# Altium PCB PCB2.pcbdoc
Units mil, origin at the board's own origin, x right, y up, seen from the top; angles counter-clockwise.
Board outline 2311.1 x 2236.23 mil, 4 copper layers (Top Layer, Inner1, 内层2, Bottom Layer); 31 components, 18 nets, 99 pads, 262 vias.
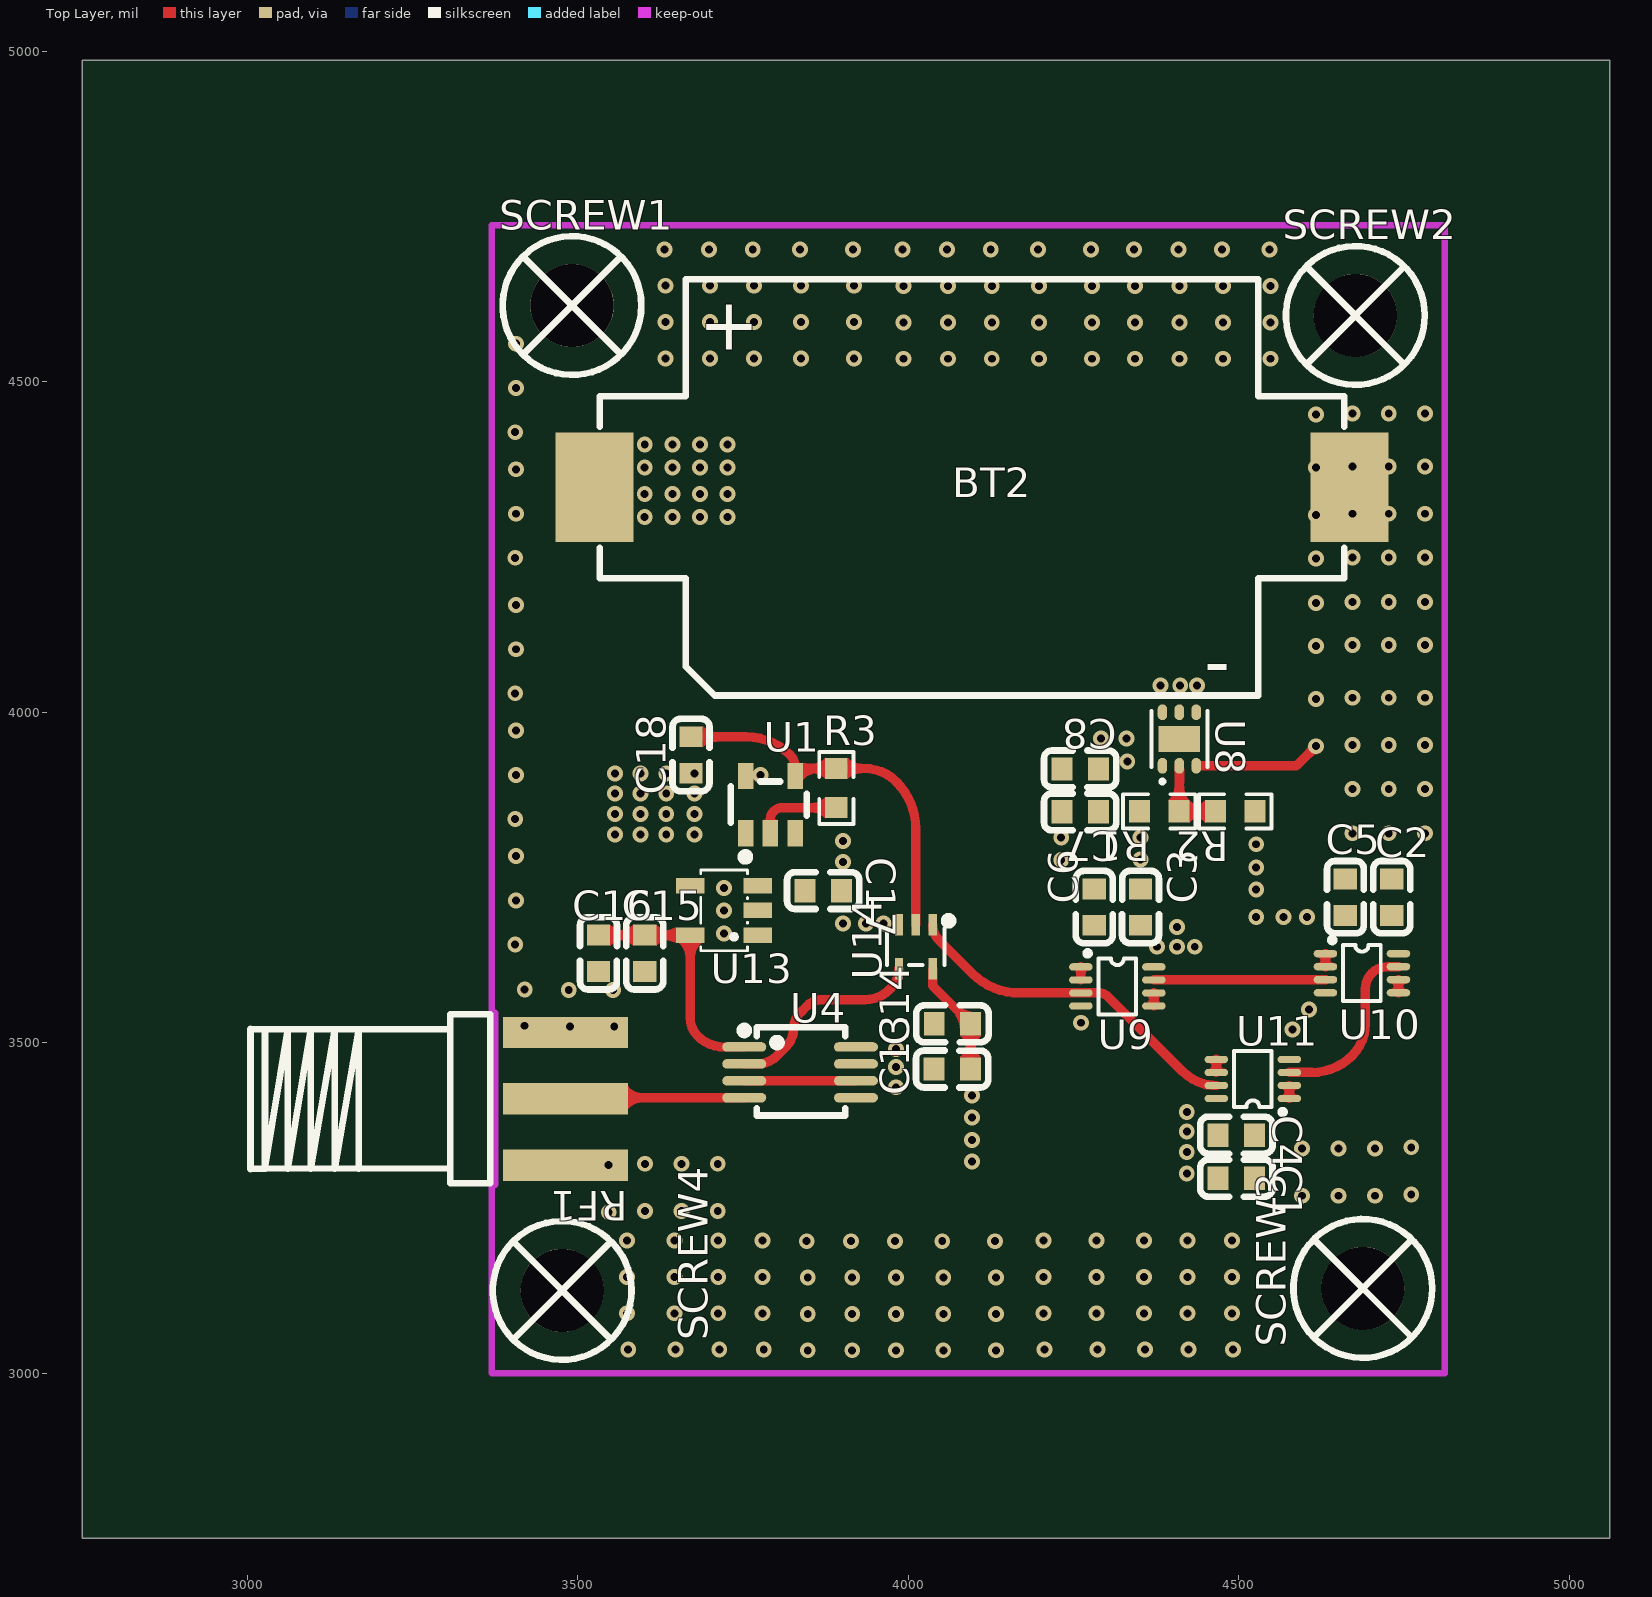
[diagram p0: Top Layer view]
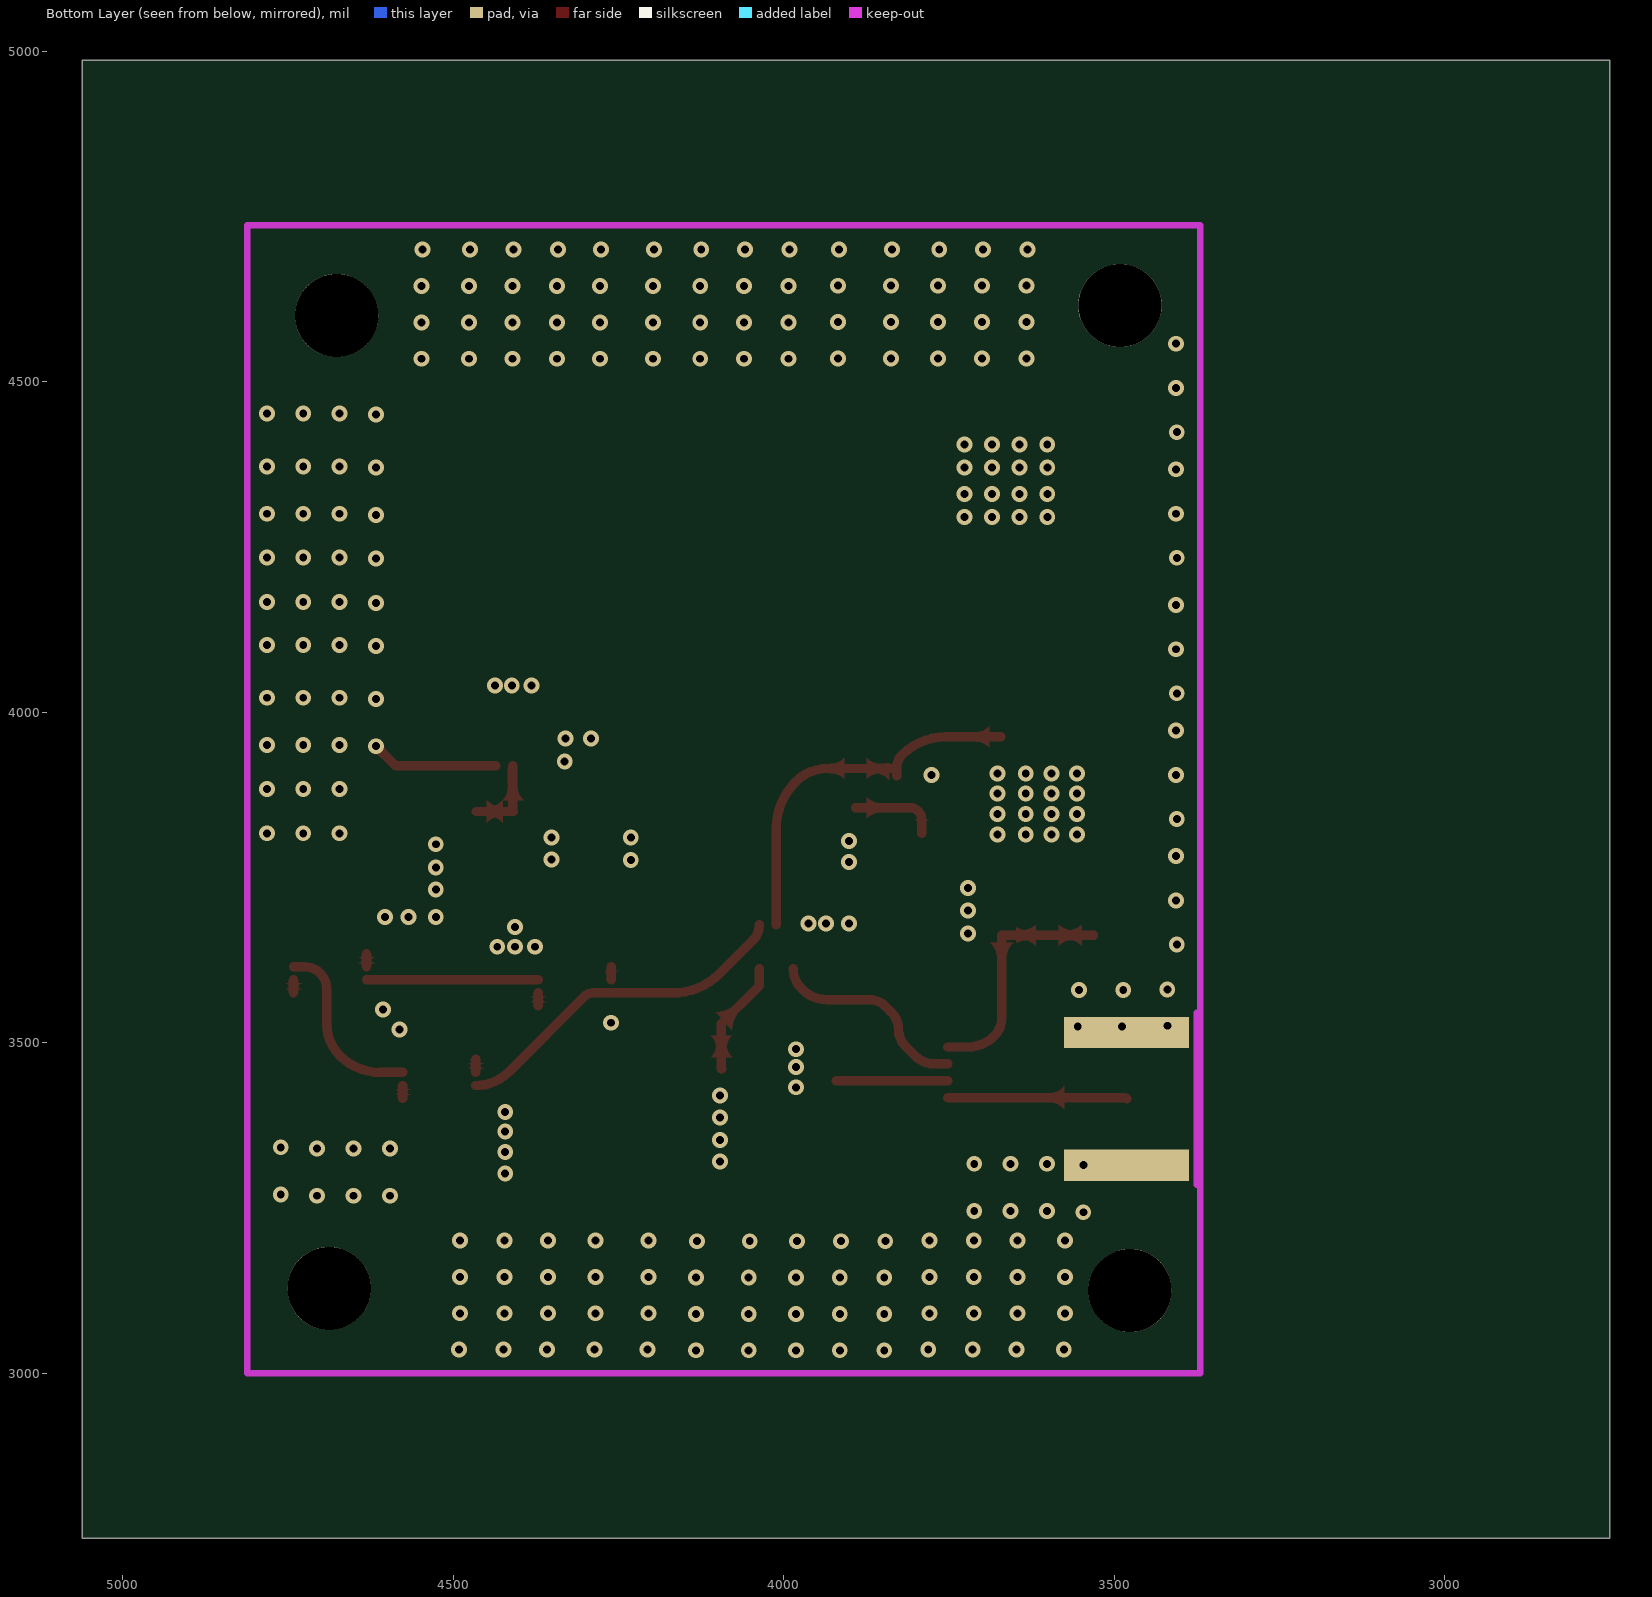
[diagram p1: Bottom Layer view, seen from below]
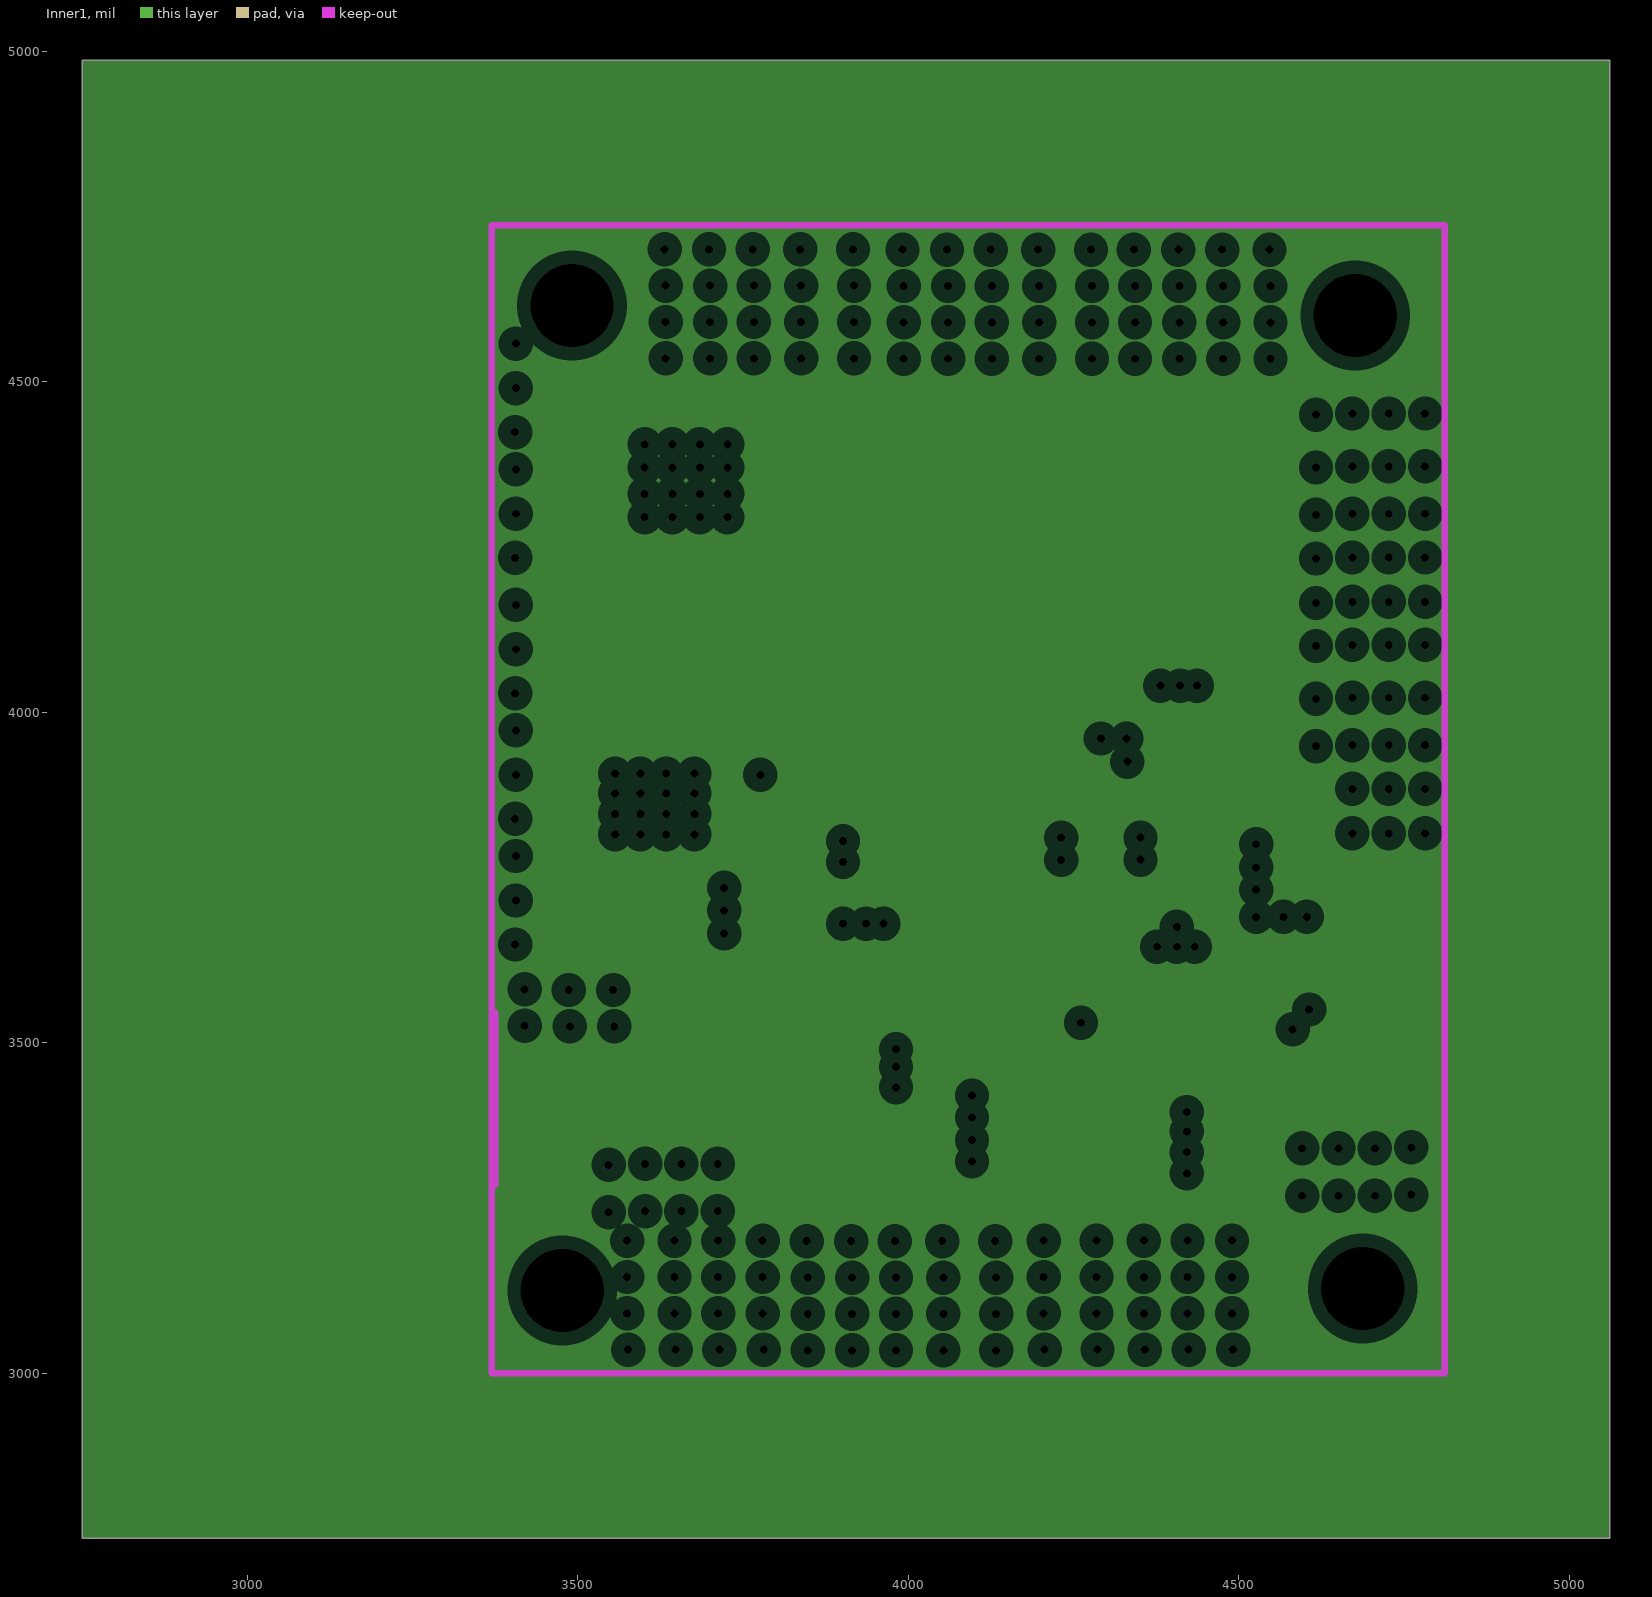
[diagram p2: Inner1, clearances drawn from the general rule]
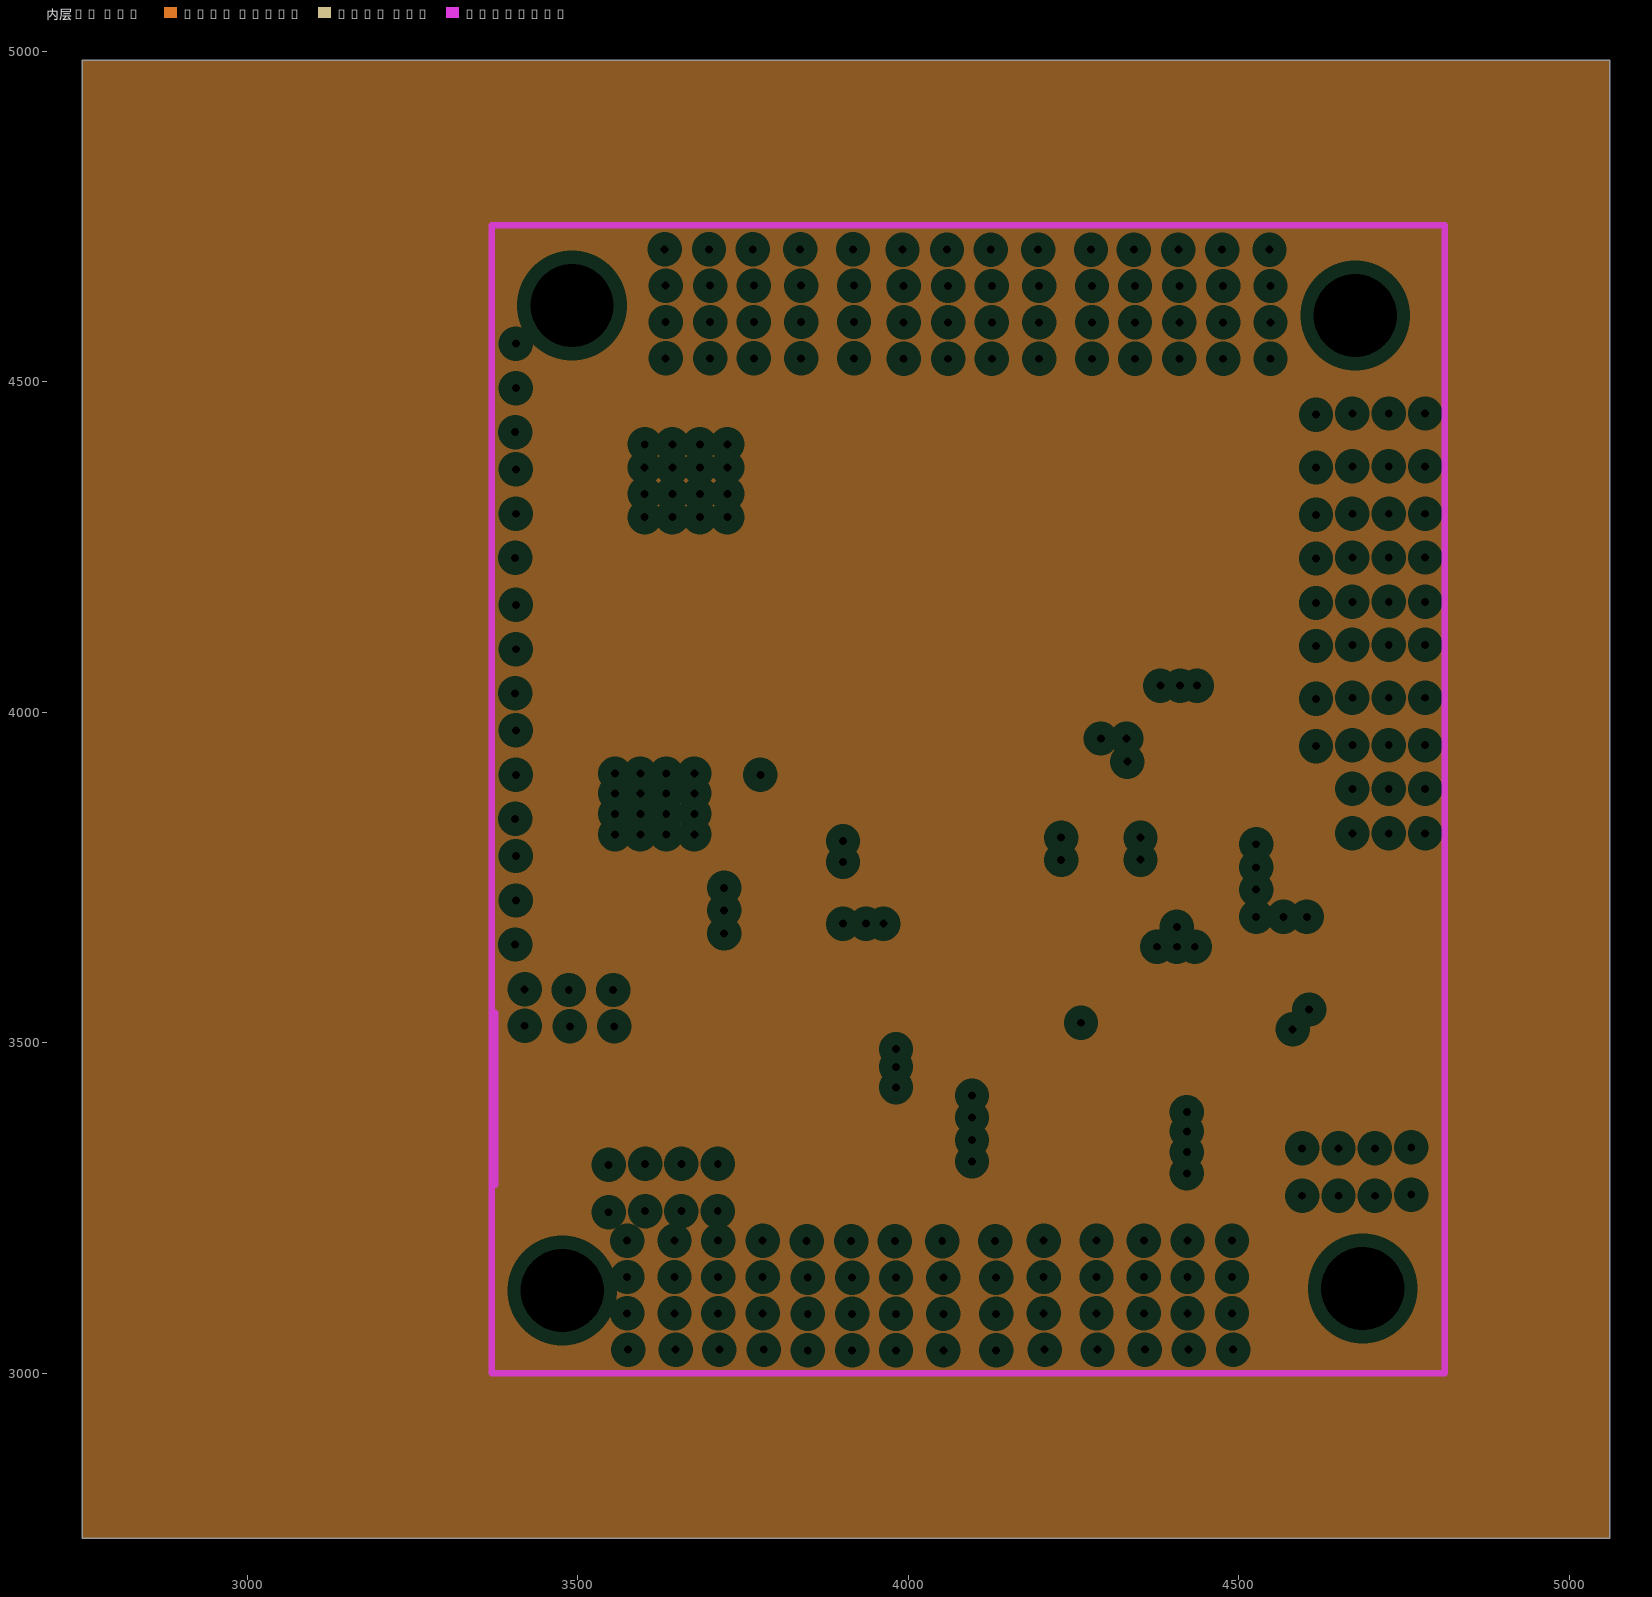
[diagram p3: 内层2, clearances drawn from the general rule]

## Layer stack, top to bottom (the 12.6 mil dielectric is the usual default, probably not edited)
Top Layer: signal copper (thickness not stored)
Dielectric: dielectric 12.6, FR-4, Dk 4.8
Inner1: plane copper (thickness not stored)
Dielectric: dielectric 12.6, FR-4, Dk 4.8
内层2: plane copper (thickness not stored)
Dielectric: dielectric 12.6, FR-4, Dk 4.8
Bottom Layer: signal copper (thickness not stored)

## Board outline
5061.1,2750 2750,2750 2750,4986.23 5061.1,4986.23

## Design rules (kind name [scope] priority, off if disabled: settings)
BoardOutlineClearance copperThickness1oz [All] p0: genericclearance=10 ignorepadtopadclearanceinfootprint=FALSE except(0: Arc-SplitContinuation Track-SplitContinuation SMDPad-SplitContinuation THPad-SplitContinuation Via-SplitContinuation Fill-SplitContinuation Poly-SplitContinuation Region-SplitContinuation Text-SplitContinuation; 6: Track-CutoutEdge SMDPad-CutoutEdge THPad-CutoutEdge Via-CutoutEdge Region-CutoutEdge; 11.8: Track-OutlineEdge SMDPad-OutlineEdge THPad-OutlineEdge Via-OutlineEdge Fill-OutlineEdge Region-OutlineEdge Poly-OutlineEdge Text-OutlineEdge Fill-CutoutEdge)
BoardOutlineClearance copperThickness2oz [All] p0: genericclearance=10 ignorepadtopadclearanceinfootprint=FALSE except(0: Arc-SplitContinuation Track-SplitContinuation SMDPad-SplitContinuation THPad-SplitContinuation Via-SplitContinuation Fill-SplitContinuation Poly-SplitContinuation Region-SplitContinuation Text-SplitContinuation; 6: Track-CutoutEdge SMDPad-CutoutEdge THPad-CutoutEdge Via-CutoutEdge Region-CutoutEdge; 11.8: Track-OutlineEdge SMDPad-OutlineEdge THPad-OutlineEdge Via-OutlineEdge Fill-OutlineEdge Region-OutlineEdge Poly-OutlineEdge Text-OutlineEdge Fill-CutoutEdge)
Clearance copperThickness1oz [(InNet('+3V') OR InNet('GND') OR InNet('VCC') OR InNet('$1N1815') OR InNet('$1N1960') OR InNet('$1N1780') OR InNet('$1N1939') OR InNet('$1N1788') OR InNet('$1N1786') OR InNet('$1N1774') OR InNet('$1N1810') OR InNet('$1N1811') OR InNet('$1N1773') OR InNet('$1N1772') OR InNet('$1N1777') OR InNet('$1N1771') OR InNet('$1N1776') OR InNet('$1N1775'))] p1: gap=7 ignorepadtopadclearanceinfootprint=FALSE except(4: Track-Track; 6: Track-SMDPad SMDPad-SMDPad Track-THPad SMDPad-THPad THPad-THPad Track-Via SMDPad-Via THPad-Via Via-Via SMDPad-Fill THPad-Fill Via-Fill Fill-Fill Track-Region SMDPad-Region THPad-Region Via-Region Region-Region Track-Poly SMDPad-Poly THPad-Poly Via-Poly Fill-Poly Region-Poly Poly-Poly Track-Text SMDPad-Text THPad-Text Via-Text Fill-Text Region-Text Poly-Text Text-Text; 6.9: Track-Hole SMDPad-Hole THPad-Hole Via-Hole Fill-Hole Region-Hole Poly-Hole Text-Hole Sheet-Hole; 11.8: Track-Fill Fill-Region Track-Sheet SMDPad-Sheet THPad-Sheet Via-Sheet Fill-Sheet Region-Sheet Poly-Sheet Text-Sheet)
Clearance copperThickness2oz [All] p1: gap=7 ignorepadtopadclearanceinfootprint=FALSE except(6: Track-SMDPad SMDPad-SMDPad Track-THPad SMDPad-THPad THPad-THPad Track-Via SMDPad-Via THPad-Via Via-Via SMDPad-Fill THPad-Fill Via-Fill Fill-Fill Track-Region SMDPad-Region THPad-Region Via-Region Region-Region Track-Poly SMDPad-Poly THPad-Poly Via-Poly Fill-Poly Region-Poly Poly-Poly Track-Text SMDPad-Text THPad-Text Via-Text Fill-Text Region-Text Poly-Text Text-Text; 6.9: Track-Hole SMDPad-Hole THPad-Hole Via-Hole Fill-Hole Region-Hole Poly-Hole Text-Hole Sheet-Hole; 8: Track-Track; 11.8: Track-Fill Fill-Region Track-Sheet SMDPad-Sheet THPad-Sheet Via-Sheet Fill-Sheet Region-Sheet Poly-Sheet Text-Sheet)
DiffPairsRouting differentialPair [All] p1: maxuncoupledlength=10 minlimit=5.9843 maxlimit=5.9843 mostfreqgap=5.9843 toplayer_minwidth=5 toplayer_prefwidth=10 toplayer_maxwidth=100 bottomlayer_minwidth=5 bottomlayer_prefwidth=10 bottomlayer_maxwidth=100
PasteMaskExpansion pasteMaskExpansion [All] p1: expansion=0
PlaneConnect innerPlane [All] p1: planeconnectstyle=Relief reliefexpansion=20 reliefentries=4 reliefconductorwidth=10 reliefairgap=10
PolygonConnect copperRegion [All] p1: connectstyle=Direct reliefentries=4 reliefconductorwidth=10 polygonreliefangle="90 Angle" airgapwidth=10
RoutingVias viaSize [All] p1: viastyle="Through Hole" holewidth=12.0078 minholewidth=11.811 maxholewidth=248.0314 width=24.0158 minwidth=19.685 maxwidth=393.7008
SolderMaskExpansion solderMaskExpansion [All] p1: useseparateexpansions=TRUE expansion=2.0079 expansionbottom=2.0079
Width copperThickness1oz [All] p1: maxlimit=100 minlimit=5 preferedwidth=10
Width copperThickness2oz [All] p1: maxlimit=100 minlimit=8 preferedwidth=10

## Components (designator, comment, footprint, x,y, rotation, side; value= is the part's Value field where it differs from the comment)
BT2 "XDCR-2032-603" BAT-SMD_XDCR-2032-603 4096.1,4340 r0 top
C1 "CAP_0603" C0603 4496.1,3295 r0 top
C2 "CAP_0603" C0603 4731.1,3720 r90 top
C3 "CAP_0603" C0603 4351.1,3705 r90 top
C4 "CGA0603X5R105K500JT" C0603 4496.1,3360 r0 top
C5 "CGA0603X5R105K500JT" C0603 4661.1,3720 r90 top
C6 "CGA0603X5R105K500JT" C0603 4281.1,3705 r90 top
C7 "CAP_0603" C0603 4259.79,3848.93 r180 top
C8 "CGA0603X5R105K500JT" C0603 4259.79,3913.93 r180 top
C13 "CAP_0603" C0603 4066.1,3460 r0 top
C14 "CGA0603X5R105K500JT" C0603 4066.55,3528.37 r0 top
C15 "CAP_0603" C0603 3601.1,3635 r90 top
C16 "CGA0603X5R105K500JT" C0603 3531.1,3635 r90 top
C17 "CAP_0603" C0603 3871.1,3730 r180 top
C18 "CAP_0603" C0603 3671.1,3935 r90 top
R1 "Res_0603" R0603 4379.36,3849.65 r0 top
R2 "Res_0603" R0603 4494.36,3849.65 r0 top
R3 "Res_0603" R0603 3891.1,3885 r90 top
RF1 "BWSMA-KE-P001" SMA-SMD_BWSMA-KE-P001 3481.1,3415 r180 top
SCREW1 "M3螺丝" M3螺丝 3491.1,4615 r0 top
SCREW2 "M3螺丝" M3螺丝 4676.1,4600 r0 top
SCREW3 "M3螺丝" M3螺丝 4687.42,3128.15 r0 top
SCREW4 "M3螺丝" M3螺丝 3476.1,3125 r0 top
U1 "SN74AUP1G14DBVR" SOT-23-5_L2.9-W1.6-P0.95-LS2.8-BR 3791.1,3860 r270 top
U4 "ADG902BRMZ" MSOP-8_L3.0-W3.0-P0.65-LS5.0-BL 3836.1,3455 r270 top
U8 "TLV75801PDRVR" WSON-6_L2.0-W2.0-P0.65-TL-EP 4409.79,3959.2 r90 top
U9 "SN74AUP3G04DCUR" VSSOP-8_L2.3-W2.0-P0.50-LS3.1-BL 4316.1,3585 r270 top
U10 "SN74AUP3G04DCUR" VSSOP-8_L2.3-W2.0-P0.50-LS3.1-BL 4686.1,3605 r270 top
U11 "SN74AUP3G04DCUR" VSSOP-8_L2.3-W2.0-P0.50-LS3.1-BL 4521.1,3445 r90 top
U13 "TPS7A0518PDBVR" SOT-23-5_L3.0-W1.7-P0.95-LS2.8-BR 3721.1,3700 r0 top
U14 "74AUP1G86GW-TP" SOT-353_L2.1-W1.3-P0.65-LS2.3-BR 4011.1,3645 r90 top

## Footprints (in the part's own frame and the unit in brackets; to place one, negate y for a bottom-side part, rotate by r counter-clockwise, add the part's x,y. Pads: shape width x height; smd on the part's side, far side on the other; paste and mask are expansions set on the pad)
BAT-SMD_XDCR-2032-603 [mm]
  rect 3x4.2 smd: 1(-14.5,0) 2(14.5,0)
  silkscreen extent -14.3,-8 14.3,8
C0603 [mm]
  rect 0.8x0.9 smd: 1(-0.7,0) 2(0.7,0)
  silkscreen extent -1.39,-0.71 1.39,0.71
M3螺丝 [mil]
  round 126 hole 126: 1(0,0)
  silkscreen extent -105,-105 105,105
MSOP-8_L3.0-W3.0-P0.65-LS5.0-BL [mil]
  oval 14.33x66.61 smd: 1(-38.39,-84.49) 2(-12.79,-84.49) 3(12.8,-84.49) 4(38.39,-84.49) 5(38.39,84.49) 6(12.8,84.49) 7(-12.79,84.49) 8(-38.39,84.49)
  silkscreen extent -69,-90 65,68
R0603 [mil]
  rect 31.75x34.02 smd: 1(-29.66,0) 2(29.66,0)
  silkscreen extent -55,-26 55,26
SMA-SMD_BWSMA-KE-P001 [mm]
  rect 4.8x1.2 smd: 1(0,-2.55) 2(0,2.55) 5(0,0)
  rect 4.8x1.2 smd far side: 3(0,2.55) 4(0,-2.55)
  Board Outline Layer lines w0.254: 2.7,3.3 2.7,-3.3 2.7,3.3
  silkscreen extent 2.89,-3.25 12.1,3.25
SOT-23-5_L2.9-W1.6-P0.95-LS2.8-BR [mm]
  rect 1x0.6 smd: 1(1.1,-0.95) 2(1.1,0) 3(1.1,0.95) 4(-1.1,0.95) 5(-1.1,-0.95)
  silkscreen extent -0.89,-1.52 2.16,1.4
SOT-23-5_L3.0-W1.7-P0.95-LS2.8-BR [mm]
  rect 1.1x0.6 smd: 1(1.3,-0.95) 2(1.3,0) 3(1.3,0.95) 4(-1.3,0.95) 5(-1.3,-0.95)
  silkscreen extent -0.9,-1.55 0.9,1.55
SOT-353_L2.1-W1.3-P0.65-LS2.3-BR [mm]
  rect 0.839x0.315 smd: 1(0.844,-0.65) 2(0.844,0) 3(0.844,0.65) 4(-0.844,0.65) 5(-0.844,-0.65)
  silkscreen extent -0.7,-1.41 1.15,1.1
VSSOP-8_L2.3-W2.0-P0.50-LS3.1-BL [mm]
  oval 0.28x0.905 smd: 1(-0.75,-1.403) 2(-0.25,-1.403) 3(0.25,-1.403) 4(0.75,-1.403) 5(0.75,1.403) 6(0.25,1.403) 7(-0.25,1.403) 8(-0.75,1.403)
  silkscreen extent -1.37,-1.24 1.08,0.72
WSON-6_L2.0-W2.0-P0.65-TL-EP [mm]
  oval 0.607x0.364 smd: 1(-1.028,0.65) 2(-1.028,0) 3(-1.028,-0.65) 4(1.028,-0.65) 5(1.028,0) 6(1.028,0.65)
  rect 1x1.6 smd: 7(0,0)
  silkscreen extent -1.71,-1.08 1.08,1.08

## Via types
v1: diameter 24.02, hole 12.01, Top Layer to Bottom Layer, 262 vias

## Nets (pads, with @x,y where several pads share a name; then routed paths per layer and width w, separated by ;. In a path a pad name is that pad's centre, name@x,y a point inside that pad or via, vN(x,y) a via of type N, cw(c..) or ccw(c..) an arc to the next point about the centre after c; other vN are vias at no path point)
$1N1771: U10.1 U10.2 | length 19.7
  Top Layer w14.2: U10.2 U10.1
$1N1772: U10.5 U10.6 | length 19.7
  Top Layer w14.2: U10.5 U10.6
$1N1773: U9.1 U9.2 | length 19.7
  Top Layer w14.2: U9.2 U9.1
$1N1774: U9.5 U9.6 | length 19.7
  Top Layer w14.2: U9.5 U9.6
$1N1775: U11.1 U11.2 | length 19.7
  Top Layer w14.2: U11.1 U11.2
$1N1776: U11.5 U11.6 | length 19.7
  Top Layer w14.2: U11.6 U11.5
$1N1777: U10.7 U11.3 | length 277.4
  Top Layer w14.2: U11.3 4610.36,3454.84 ccw(c4610.36,3540.74) 4671.1,3480 ccw(c4622.82,3528.28) 4691.1,3528.28 4691.1,3580.86 cw(c4725.25,3580.86) 4701.1,3605 cw(c4724.86,3581.24) 4724.86,3614.84 U10.7
$1N1780: R1.2 R2.1 U8.2 | length 125
  Top Layer w14.2: U8.2 4409.79,3851.5 cw(c4407.17,3851.5) R1.2 R2.1
$1N1786: U4.2 U14.4 | length 310.9
  Top Layer w14.2: U4.2 3771.63,3467.79 ccw(c3771.63,3509.48) 3773.73,3467.84 cw(c3777.75,3449.37) 3777.81,3468.28 3777.97,3468.28 ccw(c3771.63,3509.48) 3801.1,3480 3815.5,3494.39 ccw(c3789.89,3520) 3826.1,3520 cw(c3862.32,3520) 3836.71,3545.61 3846.1,3555 cw(c3870.25,3530.86) 3870.25,3565 3934.89,3565 ccw(c3934.89,3616.21) 3971.1,3580 3973.24,3582.14 ccw(c3943.63,3611.76) U14.4
$1N1788: RF1.5 U4.4 | length 270.9
  Top Layer w14.2: RF1.5 cw(c3485,3411.1) 3485,3416.61 U4.4
$1N1810: U9.7 U10.3 | length 259.6
  Top Layer w14.2: U9.7 4630.11,3594.84 ccw(c4630.11,3595.93) U10.3
$1N1811: U9.3 U11.7 U14.1 | length 528.4
  Top Layer w14.2: U14.1 ccw(c4070.08,3678.24) 4046.47,3654.63 4096.65,3604.45 ccw(c4167.36,3675.16) 4167.36,3575.16 U9.3 4288.65,3575.16 cw(c4288.65,3557.54) 4301.1,3570 4414.77,3456.33 ccw(c4465.88,3507.44) 4445.49,3438.1 ccw(c4453.58,3454.84) 4453.41,3436.24 ccw(c4465.88,3507.44) U11.7
$1N1815: C15.2 C16.2 U4.1 U13.5 | length 369.4
  Top Layer w14.2: C16.2 C15.2 3669.82,3662.56 ccw(c3669.82,3662.7) U13.5 3669.92,3537 ccw(c3708.11,3537) 3681.1,3510 ccw(c3721.2,3550.1) 3721.2,3493.39 U4.1
$1N1939: R3.1 U1.2 | length 131.1
  Top Layer w14.2: U1.2 3791.1,3837.92 cw(c3808.19,3837.92) 3796.1,3850 cw(c3808.99,3837.11) 3808.99,3855.34 R3.1
$1N1960: C18.2 R3.2 U1.4 U14.2 | length 574.4
  Top Layer w14.2: C18.2 3754.57,3962.56 cw(c3754.57,3868.46) 3821.1,3935 cw(c3803.23,3917.12) U1.4@3828.51,3917.12 ; U1.4 U1.4@3828.51,3917.12 ; U14.2 4011.1,3823.58 ccw(c3911.1,3823.58) 3981.81,3894.29 3981.1,3895 ccw(c3933.64,3847.54) 3933.64,3914.66 R3.2 3834.45,3914.66 cw(c3834.45,3923.07) U1.4@3828.51,3917.12
+3V: BT2.1 C17.2 U8.4 U8.6 U13.1 U13.3
  other v1: 3721.1,3665 3721.1,3700 3721.1,3734.09 4381.1,4040 4411.1,4040 4436.63,4040 3601.06,4295 3642.9,4295 3684.5,4295 3726.1,4295 3601.06,4330 3642.9,4330 3684.5,4330 3726.1,4330 3601.06,4370 3642.9,4370 3684.5,4370 3726.1,4370 3601.1,4405 3642.94,4405 3684.55,4405 3726.15,4405
GND: BT2.2 C1.2 C2.2 C3.2 C4.2 C5.2 C6.2 C7.2 C8.2 C13.1 C14.1 C15.1 C16.1 C17.1 C18.1 R1.1 RF1.1 RF1.2 RF1.3 RF1.4 SCREW1.1 SCREW2.1 SCREW3.1 SCREW4.1 U1.3 U4.3 U4.5 U4.6 U4.7 U4.8 U8.3 U9.4 U10.4 U11.4 U13.2 U14.3 | length 362.5
  Top Layer w14.2: U4.3 U4.6 ; U8.3 4586.91,3918.72 v1(4616.58,3948.38)
  other v1: 3576.06,3035.48 3647.72,3035.48 3713.86,3035.48 3781.1,3035.48 3847.72,3034.52 3914.96,3034.52 3981.1,3034.52 4052.76,3034.52 4132.72,3034.52 4206.1,3035.48 4286.06,3035.48 4357.72,3035.48 4423.86,3035.48 4491.1,3035.48 3574.45,3090.48 3646.1,3090.48 3712.25,3090.48 3779.49,3090.48 3847.72,3089.52 3914.96,3089.52 3981.1,3089.52 4052.76,3089.52 4132.72,3089.52 4204.49,3090.48 4284.45,3090.48 4356.1,3090.48 4422.25,3090.48 4489.49,3090.48 3574.45,3145.48 3646.1,3145.48 3712.25,3145.48 3779.49,3145.48 3847.72,3144.52 3914.96,3144.52 3981.1,3144.52 4052.76,3144.52 4132.72,3144.52 4204.49,3145.48 4284.45,3145.48 4356.1,3145.48 4422.25,3145.48 4489.49,3145.48 3574.45,3200.48 3646.1,3200.48 3712.25,3200.48 3779.49,3200.48 3846.1,3199.52 3913.34,3199.52 3979.49,3199.52 4051.14,3199.52 4131.1,3199.52 4204.49,3200.48 4284.45,3200.48 4356.1,3200.48 4422.25,3200.48 4489.49,3200.48 3546.58,3243.38 3601.58,3245 3656.58,3245 3711.58,3245 4595.62,3268.34 4650.62,3268.34 4705.62,3268.34 4760.62,3269.96 3546.58,3315.04 3601.58,3316.66 3656.58,3316.66 3711.58,3316.66 4595.62,3340 4650.62,3340 4705.62,3340 4760.62,3341.62 3981.1,3432.39 3981.1,3463.25 3981.1,3490 4581.1,3520 3419.49,3525.48 3487.72,3524.52 3554.96,3524.52 4261.1,3530 4606.1,3550 3419.49,3580.48 3486.1,3579.52 3553.34,3579.52 3405.14,3648.38 3901.1,3680 3935.8,3680 3962.26,3680 3406.1,3715 3901.1,3773.27 4231.1,3776.21 4351.1,3776.7 3406.1,3782.24 3901.1,3805 4231.1,3810 4351.1,3810 3556.1,3815 3594.48,3815 3633.6,3815 3676.1,3815 4671.58,3816.62 4726.58,3816.62 4781.58,3816.62 3405.14,3838.38 3556.1,3845.95 3594.48,3845.95 3633.6,3845.95 3676.1,3845.95 3556.1,3876.98 3594.48,3876.98 3633.6,3876.98 3676.1,3876.98 4671.58,3883.86 4726.58,3883.86 4781.58,3883.86 3406.1,3905 3556.1,3906.99 3594.48,3906.99 3633.6,3906.99 3676.1,3906.99 4671.58,3950 4726.58,3950 4781.58,3950 3406.1,3972.24 4616.58,4020.04 4671.58,4021.66 4726.58,4021.66 4781.58,4021.66 3405.14,4028.38 3406.1,4095 4616.58,4100 4671.58,4101.62 4726.58,4101.62 4781.58,4101.62 3406.1,4162.24 4616.58,4165 4671.58,4166.62 4726.58,4166.62 4781.58,4166.62 4616.58,4232.24 3405.14,4233.38 4671.58,4233.86 4726.58,4233.86 4781.58,4233.86 4616.58,4298.38 3406.1,4300 4671.58,4300 4726.58,4300 4781.58,4300 3406.1,4367.24 4616.58,4370.04 4671.58,4371.66 4726.58,4371.66 4781.58,4371.66 3405.14,4423.38 4616.58,4450 4671.58,4451.62 4726.58,4451.62 4781.58,4451.62 3406.1,4490 3632.72,4535 3699.96,4535 3766.1,4535 3837.76,4535 3917.72,4535 3992.72,4534.52 4059.96,4534.52 4126.1,4534.52 4197.76,4534.52 4277.72,4534.52 4342.72,4534.52 4409.96,4534.52 4476.1,4534.52 4547.76,4534.52 3406.1,4557.24 3632.72,4590 3699.96,4590 3766.1,4590 3837.76,4590 3917.72,4590 3992.72,4589.52 4059.96,4589.52 4126.1,4589.52 4197.76,4589.52 4277.72,4589.52 4342.72,4589.52 4409.96,4589.52 4476.1,4589.52 4547.76,4589.52 3632.72,4645 3699.96,4645 3766.1,4645 3837.76,4645 3917.72,4645 3992.72,4644.52 4059.96,4644.52 4126.1,4644.52 4197.76,4644.52 4277.72,4644.52 4342.72,4644.52 4409.96,4644.52 4476.1,4644.52 4547.76,4644.52 3631.1,4700 3698.34,4700 3764.49,4700 3836.14,4700 3916.1,4700 3991.1,4699.52 4058.34,4699.52 4124.49,4699.52 4196.14,4699.52 4276.1,4699.52 4341.1,4699.52 4408.34,4699.52 4474.49,4699.52 4546.14,4699.52
VCC: C1.1 C2.1 C3.1 C4.1 C5.1 C6.1 C7.1 C8.1 C13.2 C14.2 R2.2 U1.5 U8.1 U9.8 U10.8 U11.8 U14.5 | length 175.7
  Top Layer w14.2: U14.5 4036.69,3585.78 C14.2 4094.11,3460.45 C13.2
  other v1: 4421.1,3302.24 4096.1,3320.06 4421.1,3334.25 4096.1,3352.4 4421.1,3365.61 4096.1,3386.7 4421.1,3395 4096.1,3420 4376.1,3645 4406.1,3645 4433.15,3645 4406.1,3675 4526.1,3690.17 4567.42,3690.17 4602.69,3690.17 4526.1,3731.33 4526.1,3765.13 4526.1,3800 3776.1,3905 4331.1,3925 4291.1,3960 4329.84,3960
pads on no net: U1.1 U8.5 U8.7 U13.4

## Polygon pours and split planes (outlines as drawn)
$1N1960 on Top Layer (solid, remove dead copper, pour order 0): 3533.93,3943.21 3533.93,4072.82 3687.89,4072.82 3687.89,3943.21
GND on Top Layer (solid, remove dead copper, pour order 2): 3536.1,3795 3536.1,3925 3691.1,3925 3691.1,3795
+3V on Bottom Layer (solid, remove dead copper, pour order 52): 3581.1,4425 3581.1,4260 3751.1,4260 3751.1,4422.77 3748.87,4425
+3V on Bottom Layer (solid, remove dead copper, pour order 54): 3706.1,3655 3751.1,3655 3751.1,4420 3706.1,4420
+3V on Bottom Layer (solid, remove dead copper, pour order 56): 3726.1,4060 4451.1,4060 4451.1,4025.03 3727.07,4025.03 3726.1,4026
GND on Top Layer (solid, remove dead copper, pour order 4): 3886.1,3505 3886.1,3405 4056.1,3405 4056.1,3505.19 3885.91,3505.19
+3V on Top Layer (solid, remove dead copper, pour order 6): 3466.1,4425 3756.1,4425 3756.1,4255 3466.1,4255
+3V on Top Layer (solid, remove dead copper, pour order 8): 3776.1,3750 3865.48,3750 3865.48,3711.03 3823.4,3711.03 3823.4,3723.64 3777.47,3723.64 3776.1,3725
GND on Top Layer (solid, remove dead copper, pour order 10): 4024.03,3544.13 4024.03,3491.29 4027.36,3487.96 4055.07,3487.96 4055.52,3488.4 4055.52,3528.37 4039.76,3544.13
+3V on Top Layer (solid, remove dead copper, pour order 12): 3771.1,3750 3711.1,3750 3711.1,3649.6 3770.7,3649.6 3771.1,3650 3771.1,3675.51 3738.22,3675.51 3738.22,3725.16 3771.76,3725.16 3771.76,3749.35
+3V on Top Layer (solid, remove dead copper, pour order 14): 4366.1,3985.36 4366.1,4055 4448.33,4055 4448.33,3986.23 4427.43,3986.23 4427.43,4019.33 4390.19,4019.33 4390.19,3985.36
VCC on Top Layer (solid, remove dead copper, pour order 16): 3756.1,3925 3793.6,3925 3793.6,3880 3755,3880 3755,3923.89
VCC on Top Layer (solid, remove dead copper, pour order 18): 4270.19,3929.67 4270.82,3929.04 4270.82,3830.52 4306.1,3830.52 4306.1,3900 4305.89,3905 4391.1,3905 4391.1,3931.3 4271.82,3931.3
VCC on Top Layer (solid, remove dead copper, pour order 20): 4271.51,3913.93 4271.51,3979.41 4349.9,3979.41 4349.9,3912.8 4272.64,3912.8
VCC on Top Layer (solid, remove dead copper, pour order 22): 4261.1,3695 4448.3,3695 4448.3,3610 4354.1,3610 4354.1,3650.28 4265.82,3650.28 4261.1,3655
VCC on Top Layer (solid, remove dead copper, pour order 24): 4636.72,3668.85 4717.25,3668.85 4721.1,3665 4721.1,3628.65 4759.75,3628.65 4761.1,3630 4761.1,3708.97 4633.15,3708.97 4633.15,3672.42
VCC on Top Layer (solid, remove dead copper, pour order 26): 4645.34,3665.28 4506.1,3665.28 4506.1,3873.41 4508.35,3875.66 4548.9,3875.66 4566.1,3858.45 4566.1,3710 4641.1,3710 4646.1,3705 4646.1,3666.04
VCC on Top Layer (solid, remove dead copper, pour order 28): 4401.1,3420.81 4401.1,3270.63 4486.1,3270.63 4486.1,3420.81
GND on Top Layer (solid, remove dead copper, pour order 30): 4633.16,3731.03 4805.62,3731.03 4805.62,4715.48 4796.1,4725 3381.1,4725 3376.1,4720 3376.1,4510 3381.1,4505 4581.1,4505 4591.1,4495 4591.1,3920 4636.1,3875 4636.1,3733.97
GND on Top Layer (solid, remove dead copper, pour order 32): 3374.8,3338.62 3374.8,3005 4806.1,3005 4811.1,3000 4811.1,3747.66 4778.44,3747.66 4776.1,3750 4776.1,3385 4775.46,3384.36 4506.2,3384.36 4506.2,3225 3761.1,3225 3761.1,3337.01 3759.5,3338.62
GND on Top Layer (solid, remove dead copper, pour order 34): 3374.8,3491.24 3626.1,3491.24 3626.1,3623.97 3435.24,3623.97 3435.24,4550.88 3369.88,4550.88 3369.88,3496.17
GND on Top Layer (solid, remove dead copper, pour order 36): 4217.26,3929.69 4217.26,3718.84 4221.1,3715 4371.1,3715 4371.1,3756.15 4367.53,3759.72 4250.23,3759.72 4250.23,3930 4217.57,3930
GND on Top Layer (solid, remove dead copper, pour order 38): 4331.1,3870 4331.1,3747.53 4370.84,3747.53 4370.84,3869.74 4371.1,3870
GND on Top Layer (solid, remove dead copper, pour order 40): 3985.51,3662.54 3881.1,3662.54 3881.1,3749.43 3919.47,3749.43 3919.47,3693.9 3986.1,3693.9 3986.1,3663.13
GND on Top Layer (solid, remove dead copper, pour order 42): 3882.13,3730 3882.13,3794.83 3816.27,3794.83 3816.1,3795 3816.1,3821.94 3919.16,3821.94 3921.1,3820 3921.1,3710 3916.1,3705 3907.13,3705
GND on Top Layer (solid, remove dead copper, pour order 44): 4558.02,3474.53 4594.89,3474.53 4594.89,3513.79 4646.1,3565 4646.1,3580.63 4616.1,3580.63 4558.02,3522.54
GND on Top Layer (solid, remove dead copper, pour order 46): 4241.1,3560 4241.1,3500 4281.1,3500 4281.1,3560
GND on Top Layer (solid, remove dead copper, pour order 48): 3772.29,3712.96 3795,3712.96 3817.96,3690 3914.88,3690 3914.88,3662.44 3818.67,3662.44 3772.29,3708.82
VCC on Top Layer (solid, remove dead copper, pour order 50): 4078.9,3528.37 4078.9,3303.26 4111.1,3303.26 4111.1,3544.11 4094.64,3544.11

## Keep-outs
Board Outline Layer:
  lines w10: 3369.88,3000 4811.1,3000 4811.1,4736.23 3369.88,4736.23 3369.88,3000

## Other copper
Top Layer:
  region net $1N1788: 3704.17,3409.51 3704.17,3423.71 3725.47,3423.78 3725.47,3409.44
  region net $1N1788: 3596.89,3423.71 3596.89,3409.51 ccw(c3596.89,3382.89) 3575.59,3398.86 3575.59,3434.36 ccw(c3596.89,3450.34)
  region net GND: 3799.05,3449.3 3799.05,3435.1 3777.75,3435.03 3777.75,3449.37
  region net GND: 3873.15,3435.1 3873.15,3449.3 3894.45,3449.37 3894.45,3435.03
  region net $1N1815: 3677.02,3629.49 3662.82,3629.49 ccw(c3636.19,3629.49) 3652.17,3650.79 3687.67,3650.79 ccw(c3703.64,3629.49)
  region net $1N1815: 3570.12,3669.66 3570.12,3655.46 ccw(c3570.12,3624.91) 3548.82,3646.81 3548.82,3678.31 ccw(c3570.12,3700.21)
  region net $1N1815: 3562.09,3655.46 3562.09,3669.66 ccw(c3562.09,3700.21) 3583.39,3678.31 3583.39,3646.81 ccw(c3562.09,3624.91)
  region net $1N1815: 3640.12,3669.66 3640.12,3655.46 ccw(c3640.12,3624.91) 3618.82,3646.81 3618.82,3678.31 ccw(c3640.12,3700.21)
  region net $1N1815: 3626.96,3655.46 3626.96,3669.66 ccw(c3626.96,3719.78) 3648.26,3674.41 3648.26,3650.79 ccw(c3626.96,3604.56)
  region net $1N1776: 4458.78,3474.53 4472.98,3474.53 4472.8,3469.32 4472.76,3466.93 4472.93,3464.78 4473.42,3462.97 4473.84,3462.21 4474.38,3461.57 4475.07,3461.05 4475.93,3460.67 4476.96,3460.43 4478.19,3460.35 4453.58,3460.35 4454.81,3460.43 4455.84,3460.67 4456.69,3461.05 4457.38,3461.57 4457.93,3462.21 4458.34,3462.97 4458.84,3464.78 4459.01,3466.93 4458.97,3469.32
  region net $1N1776: 4472.98,3454.84 4458.78,3454.84 4458.97,3460.05 4459.01,3462.44 4458.84,3464.59 4458.34,3466.4 4457.93,3467.16 4457.38,3467.8 4456.69,3468.32 4455.84,3468.7 4454.81,3468.94 4453.58,3469.02 4478.19,3469.02 4476.96,3468.94 4475.93,3468.7 4475.07,3468.32 4474.38,3467.8 4473.84,3467.16 4473.42,3466.4 4472.93,3464.59 4472.76,3462.44 4472.8,3460.05
  region net $1N1775: 4583.42,3415.47 4569.22,3415.47 4569.41,3420.68 4569.45,3423.07 4569.28,3425.22 4568.78,3427.03 4568.37,3427.79 4567.82,3428.43 4567.13,3428.95 4566.28,3429.33 4565.25,3429.57 4564.02,3429.65 4588.63,3429.65 4587.4,3429.57 4586.37,3429.33 4585.51,3428.95 4584.82,3428.43 4584.28,3427.79 4583.86,3427.03 4583.37,3425.22 4583.2,3423.07 4583.24,3420.68
  region net $1N1775: 4569.22,3435.16 4583.42,3435.16 4583.24,3429.95 4583.2,3427.56 4583.37,3425.41 4583.86,3423.6 4584.28,3422.84 4584.82,3422.2 4585.51,3421.68 4586.37,3421.3 4587.4,3421.06 4588.63,3420.98 4564.02,3420.98 4565.25,3421.06 4566.28,3421.3 4567.13,3421.68 4567.82,3422.2 4568.37,3422.84 4568.78,3423.6 4569.28,3425.41 4569.45,3427.56 4569.41,3429.95
  region net $1N1771: 4623.78,3634.53 4637.98,3634.53 4637.8,3629.32 4637.76,3626.93 4637.93,3624.78 4638.42,3622.97 4638.84,3622.21 4639.38,3621.57 4640.07,3621.05 4640.93,3620.67 4641.96,3620.43 4643.19,3620.35 4618.58,3620.35 4619.81,3620.43 4620.84,3620.67 4621.69,3621.05 4622.38,3621.57 4622.93,3622.21 4623.34,3622.97 4623.84,3624.78 4624.01,3626.93 4623.97,3629.32
  region net $1N1771: 4637.98,3614.84 4623.78,3614.84 4623.97,3620.05 4624.01,3622.44 4623.84,3624.59 4623.34,3626.4 4622.93,3627.16 4622.38,3627.8 4621.69,3628.32 4620.84,3628.7 4619.81,3628.94 4618.58,3629.02 4643.19,3629.02 4641.96,3628.94 4640.93,3628.7 4640.07,3628.32 4639.38,3627.8 4638.84,3627.16 4638.42,3626.4 4637.93,3624.59 4637.76,3622.44 4637.8,3620.05
  region net $1N1772: 4734.22,3595.16 4748.42,3595.16 4748.24,3589.95 4748.2,3587.56 4748.37,3585.41 4748.86,3583.6 4749.28,3582.84 4749.82,3582.2 4750.51,3581.68 4751.37,3581.3 4752.4,3581.06 4753.63,3580.98 4729.02,3580.98 4730.25,3581.06 4731.28,3581.3 4732.13,3581.68 4732.82,3582.2 4733.37,3582.84 4733.78,3583.6 4734.28,3585.41 4734.45,3587.56 4734.41,3589.95
  region net $1N1772: 4748.42,3575.47 4734.22,3575.47 4734.41,3580.68 4734.45,3583.07 4734.28,3585.22 4733.78,3587.03 4733.37,3587.79 4732.82,3588.43 4732.13,3588.95 4731.28,3589.33 4730.25,3589.57 4729.02,3589.65 4753.63,3589.65 4752.4,3589.57 4751.37,3589.33 4750.51,3588.95 4749.82,3588.43 4749.28,3587.79 4748.86,3587.03 4748.37,3585.22 4748.2,3583.07 4748.24,3580.68
  region net $1N1780: 4416.89,3892.63 4402.69,3892.63 4402.63,3913.93 4416.96,3913.93
  region net $1N1780: 4402.69,3887.96 4416.89,3887.96 ccw(c4449.22,3887.96) 4424.9,3866.66 4393.15,3866.66 ccw(c4374.15,3887.96)
  region net $1N1780: 4446.2,3856.75 4446.2,3842.55 ccw(c4446.2,3814.7) 4424.9,3832.64 4424.9,3866.66 ccw(c4446.2,3884.6)
  region net $1N1780: 4427.53,3842.55 4427.53,3856.75 ccw(c4427.53,3884.6) 4448.83,3866.66 4448.83,3832.64 ccw(c4427.53,3814.7)
  region net $1N1960: 3710.12,3969.66 3710.12,3955.46 ccw(c3710.12,3924.91) 3688.82,3946.81 3688.82,3978.31 ccw(c3710.12,4000.21)
  region net $1N1960: 3852.8,3907.56 3852.8,3921.76 ccw(c3852.8,3952) 3874.09,3930.54 3874.09,3898.78 ccw(c3852.8,3877.32)
  region net $1N1960: 3861.62,3921.76 3861.62,3907.56 ccw(c3861.62,3880.93) 3840.32,3896.91 3840.32,3923 ccw(c3861.62,4105.61)
  region net $1N1939: 3784,3837.92 3798.2,3837.92 ccw(c3802.91,3844.36) 3802.91,3836.38 3779.29,3836.38 ccw(c3779.29,3844.36)
  region net $1N1939: 3852.8,3848.24 3852.8,3862.44 ccw(c3852.8,3892.68) 3874.09,3871.22 3874.09,3839.46 ccw(c3852.8,3818)
  region net $1N1960: 3929.41,3921.76 3929.41,3907.56 ccw(c3929.41,3877.32) 3908.11,3898.78 3908.11,3930.54 ccw(c3929.41,3952)
  region net GND: 4610.04,3931.8 4600,3941.84 4601.63,3943.48 4603.06,3945.15 4604.11,3946.99 4604.44,3948.02 4604.6,3949.14 4617.34,3936.4 4616.22,3936.24 4615.19,3935.91 4613.35,3934.86 4611.68,3933.43
  region net VCC: 4087.01,3499.02 4101.21,3499.02 ccw(c4132.96,3499.02) 4109.41,3477.72 4077.91,3477.72 ccw(c4057.51,3499.02)
  region net VCC: 4101.21,3489.35 4087.01,3489.35 ccw(c4056.45,3489.35) 4078.36,3510.65 4109.86,3510.65 ccw(c4131.76,3489.35)
  region net VCC: 4070.83,3541.6 4078.9,3553.61 ccw(c4101.49,3583.74) 4101.49,3546.08 4078.36,3519.01 ccw(c4040.71,3519.01)
  region net $1N1774: 4378.42,3555.47 4364.22,3555.47 4364.41,3560.68 4364.45,3563.07 4364.28,3565.22 4363.78,3567.03 4363.37,3567.79 4362.82,3568.43 4362.13,3568.95 4361.28,3569.33 4360.25,3569.57 4359.02,3569.65 4383.63,3569.65 4382.4,3569.57 4381.37,3569.33 4380.51,3568.95 4379.82,3568.43 4379.28,3567.79 4378.86,3567.03 4378.37,3565.22 4378.2,3563.07 4378.24,3560.68
  region net $1N1774: 4364.22,3575.16 4378.42,3575.16 4378.24,3569.95 4378.2,3567.56 4378.37,3565.41 4378.86,3563.6 4379.28,3562.84 4379.82,3562.2 4380.51,3561.68 4381.37,3561.3 4382.4,3561.06 4383.63,3560.98 4359.02,3560.98 4360.25,3561.06 4361.28,3561.3 4362.13,3561.68 4362.82,3562.2 4363.37,3562.84 4363.78,3563.6 4364.28,3565.41 4364.45,3567.56 4364.41,3569.95
  region net $1N1773: 4267.98,3594.84 4253.78,3594.84 4253.97,3600.05 4254.01,3602.44 4253.84,3604.59 4253.34,3606.4 4252.93,3607.16 4252.38,3607.8 4251.69,3608.32 4250.84,3608.7 4249.81,3608.94 4248.58,3609.02 4273.19,3609.02 4271.96,3608.94 4270.93,3608.7 4270.07,3608.32 4269.38,3607.8 4268.84,3607.16 4268.42,3606.4 4267.93,3604.59 4267.76,3602.44 4267.8,3600.05

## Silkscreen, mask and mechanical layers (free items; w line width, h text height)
Top Solder Mask Layer:
  region: 3532.89,3944.25 3532.89,4071.79 3686.86,4071.79 3686.86,3944.25
  region: 3691.1,3925 3691.1,3795 3536.1,3795 3536.1,3925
